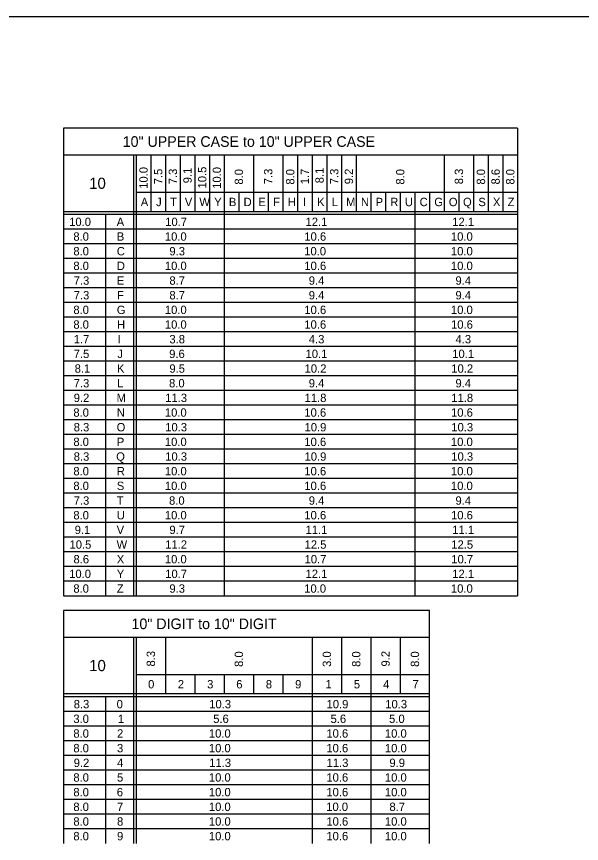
# Model space of a CAD drawing. Extents: x 637580 to 641849, y 297270 to 299646.
# Drawn here: x 640533.1 to 640735.3, y 298740.6 to 299036.6 of the extents above; entities that cross this region are included whole.
import ezdxf

# ---------------------------------------------------------------- set-up
doc = ezdxf.new("R2010")
doc.units = 0
doc.layers.add('1', color=7, linetype='Continuous')
doc.layers.add('2', color=7, linetype='Continuous')

msp = doc.modelspace()

# ---------------------------------------------------------------- linework, layer by layer
at = {"layer": '1'}
msp.add_line((640143.31, 299036.63), (640929.31, 299036.63), dxfattribs=at)
at = {"layer": '2'}
for p, q in [((640712.41, 298996.63), (640549.91, 298996.63)), ((640549.91, 298996.63), (640549.91, 298829.25)), ((640712.41, 298996.63), (640712.41, 298829.25)), ((640549.91, 298987.13), (640712.41, 298987.13)), ((640574.91, 298987.13), (640574.91, 298829.25)), ((640575.91, 298987.13), (640575.91, 298829.25)), ((640581.16, 298987.13), (640581.16, 298966.75)), ((640586.41, 298987.13), (640586.41, 298966.75)), ((640591.66, 298987.13), (640591.66, 298966.75)), ((640596.91, 298987.13), (640596.91, 298966.75)), ((640602.16, 298987.13), (640602.16, 298966.75)), ((640607.41, 298987.13), (640607.41, 298829.25)), ((640617.91, 298987.13), (640617.91, 298966.75)), ((640628.41, 298987.13), (640628.41, 298966.75)), ((640633.66, 298987.13), (640633.66, 298966.75)), ((640638.91, 298987.13), (640638.91, 298966.75)), ((640644.16, 298987.13), (640644.16, 298966.75)), ((640649.41, 298987.13), (640649.41, 298966.75)), ((640654.66, 298987.13), (640654.66, 298966.75)), ((640686.16, 298987.13), (640686.16, 298966.75)), ((640696.66, 298987.13), (640696.66, 298966.75)), ((640701.91, 298987.13), (640701.91, 298966.75)), ((640707.16, 298987.13), (640707.16, 298966.75)), ((640575.91, 298973.75), (640712.41, 298973.75)), ((640612.66, 298973.75), (640612.66, 298966.75)), ((640623.16, 298973.75), (640623.16, 298966.75)), ((640659.91, 298973.75), (640659.91, 298966.75)), ((640665.16, 298973.75), (640665.16, 298966.75)), ((640670.41, 298973.75), (640670.41, 298966.75)), ((640670.41, 298973.75), (640670.41, 298966.75)), ((640675.66, 298973.75), (640675.66, 298829.25)), ((640680.91, 298973.75), (640680.91, 298966.75)), ((640691.41, 298973.75), (640691.41, 298966.75)), ((640712.41, 298966.75), (640549.91, 298966.75)), ((640712.41, 298965.75), (640549.91, 298965.75)), ((640564.91, 298965.75), (640564.91, 298829.25)), ((640712.41, 298960.5), (640549.91, 298960.5)), ((640712.41, 298955.25), (640549.91, 298955.25)), ((640712.41, 298950), (640549.91, 298950)), ((640712.41, 298944.75), (640549.91, 298944.75)), ((640712.41, 298939.5), (640549.91, 298939.5)), ((640712.41, 298934.25), (640549.91, 298934.25)), ((640712.41, 298929), (640549.91, 298929)), ((640712.41, 298923.75), (640549.91, 298923.75)), ((640712.41, 298918.5), (640549.91, 298918.5)), ((640712.41, 298913.25), (640549.91, 298913.25)), ((640712.41, 298908), (640549.91, 298908)), ((640712.41, 298902.75), (640549.91, 298902.75)), ((640712.41, 298897.5), (640549.91, 298897.5)), ((640712.41, 298892.25), (640549.91, 298892.25)), ((640712.41, 298887), (640549.91, 298887)), ((640712.41, 298881.75), (640549.91, 298881.75)), ((640712.41, 298876.5), (640549.91, 298876.5)), ((640712.41, 298871.25), (640549.91, 298871.25)), ((640712.41, 298866), (640549.91, 298866)), ((640712.41, 298860.75), (640549.91, 298860.75)), ((640712.41, 298855.5), (640549.91, 298855.5)), ((640712.41, 298850.25), (640549.91, 298850.25)), ((640712.41, 298845), (640549.91, 298845)), ((640712.41, 298839.75), (640549.91, 298839.75)), ((640712.41, 298834.5), (640549.91, 298834.5)), ((640549.91, 298829.25), (640549.91, 298829.25)), ((640549.91, 298829.25), (640712.41, 298829.25)), ((640680.91, 298824), (640549.91, 298824)), ((640549.91, 298824), (640549.91, 298740.63)), ((640680.91, 298740.63), (640680.91, 298824)), ((640549.91, 298814.5), (640680.91, 298814.5)), ((640574.91, 298814.5), (640574.91, 298740.63)), ((640575.91, 298814.5), (640575.91, 298740.63)), ((640586.41, 298814.5), (640586.41, 298794.13)), ((640638.91, 298814.5), (640638.91, 298740.63)), ((640649.41, 298814.5), (640649.41, 298794.13)), ((640659.91, 298814.5), (640659.91, 298740.63)), ((640670.41, 298814.5), (640670.41, 298794.13)), ((640575.91, 298801.13), (640680.91, 298801.13)), ((640596.91, 298801.13), (640596.91, 298794.13)), ((640607.41, 298801.13), (640607.41, 298794.13)), ((640617.91, 298801.13), (640617.91, 298794.13)), ((640628.41, 298801.13), (640628.41, 298794.13)), ((640680.91, 298794.13), (640549.91, 298794.13)), ((640680.91, 298793.13), (640549.91, 298793.13)), ((640564.91, 298793.13), (640564.91, 298740.63)), ((640680.91, 298787.88), (640549.91, 298787.88)), ((640680.91, 298782.63), (640549.91, 298782.63)), ((640680.91, 298777.38), (640549.91, 298777.38)), ((640680.91, 298772.13), (640549.91, 298772.13)), ((640680.91, 298766.88), (640549.91, 298766.88)), ((640680.91, 298761.63), (640549.91, 298761.63)), ((640680.91, 298756.38), (640549.91, 298756.38)), ((640680.91, 298751.13), (640549.91, 298751.13)), ((640680.91, 298745.88), (640549.91, 298745.88))]:
    msp.add_line(p, q, dxfattribs=at)

# ---------------------------------------------------------------- texts
for s, height, p in [('10" UPPER CASE to 10" UPPER CASE', 3.8, (640571.1, 298989.98)), ('10', 4, (640559.1, 298974.94)), ('A', 3, (640577.56, 298968.75)), ('J', 3, (640583.04, 298968.75)), ('T', 3, (640588.04, 298968.75)), ('V', 3, (640593.31, 298968.75)), ('W', 3, (640598.53, 298968.75)), ('Y', 3, (640603.84, 298968.75)), ('B', 3, (640609.1, 298968.75)), ('D', 3, (640614.35, 298968.75)), ('E', 3, (640619.62, 298968.75)), ('F', 3, (640624.92, 298968.75)), ('H', 3, (640630.19, 298968.75)), ('I', 3, (640635.6, 298968.75)), ('K', 3, (640640.69, 298968.75)), ('L', 3, (640645.94, 298968.75)), ('M', 3, (640651.03, 298968.75)), ('N', 3, (640656.35, 298968.75)), ('P', 3, (640661.6, 298968.75)), ('R', 3, (640666.85, 298968.75)), ('U', 3, (640672.09, 298968.75)), ('C', 3, (640677.35, 298968.75)), ('G', 3, (640682.6, 298968.75)), ('O', 3, (640687.81, 298968.75)), ('Q', 3, (640692.88, 298968.75)), ('S', 3, (640698.37, 298968.75)), ('X', 3, (640703.59, 298968.75)), ('Z', 3, (640708.85, 298968.75)), ('10.0', 3, (640551.93, 298961.63)), ('A', 3, (640568.93, 298961.63)), ('10.7', 3, (640586.31, 298961.63)), ('12.1', 3, (640636.53, 298961.63)), ('12.1', 3, (640689.03, 298961.63)), ('8.0', 3, (640553.43, 298956.38)), ('B', 3, (640568.98, 298956.38)), ('10.0', 3, (640586.18, 298956.38)), ('10.6', 3, (640636.1, 298956.38)), ('10.0', 3, (640688.56, 298956.38)), ('8.0', 3, (640553.43, 298951.13)), ('C', 3, (640568.98, 298951.13)), ('9.3', 3, (640587.81, 298951.13)), ('10.0', 3, (640636.06, 298951.13)), ('10.0', 3, (640688.56, 298951.13)), ('8.0', 3, (640553.43, 298945.88)), ('D', 3, (640568.98, 298945.88)), ('10.0', 3, (640586.18, 298945.88)), ('10.6', 3, (640636.1, 298945.88)), ('10.0', 3, (640688.56, 298945.88)), ('7.3', 3, (640553.56, 298940.63)), ('E', 3, (640568.99, 298940.63)), ('8.7', 3, (640587.81, 298940.63)), ('9.4', 3, (640637.69, 298940.63)), ('9.4', 3, (640690.19, 298940.63)), ('7.3', 3, (640553.56, 298935.38)), ('F', 3, (640569.05, 298935.38)), ('8.7', 3, (640587.81, 298935.38)), ('9.4', 3, (640637.69, 298935.38)), ('9.4', 3, (640690.19, 298935.38)), ('8.0', 3, (640553.43, 298930.13)), ('G', 3, (640568.98, 298930.13)), ('10.0', 3, (640586.18, 298930.13)), ('10.6', 3, (640636.1, 298930.13)), ('10.0', 3, (640688.56, 298930.13)), ('8.0', 3, (640553.43, 298924.88)), ('H', 3, (640569.06, 298924.88)), ('10.0', 3, (640586.18, 298924.88)), ('10.6', 3, (640636.1, 298924.88)), ('10.6', 3, (640688.6, 298924.88)), ('1.7', 3, (640553.56, 298919.63)), ('I', 3, (640569.23, 298919.63)), ('3.8', 3, (640587.81, 298919.63)), ('4.3', 3, (640637.69, 298919.63)), ('4.3', 3, (640690.19, 298919.63)), ('7.5', 3, (640553.56, 298914.38)), ('J', 3, (640569.17, 298914.38)), ('9.6', 3, (640587.73, 298914.38)), ('10.1', 3, (640636.53, 298914.38)), ('10.1', 3, (640689.03, 298914.38)), ('8.1', 3, (640553.9, 298909.13)), ('K', 3, (640569.06, 298909.13)), ('9.5', 3, (640587.81, 298909.13)), ('10.2', 3, (640636.19, 298909.13)), ('10.2', 3, (640688.69, 298909.13)), ('7.3', 3, (640553.56, 298903.88)), ('L', 3, (640569.06, 298903.88)), ('8.0', 3, (640587.68, 298903.88)), ('9.4', 3, (640637.69, 298903.88)), ('9.4', 3, (640690.19, 298903.88)), ('9.2', 3, (640553.56, 298898.63)), ('M', 3, (640568.91, 298898.63)), ('11.3', 3, (640586.31, 298898.63)), ('11.8', 3, (640636.19, 298898.63)), ('11.8', 3, (640688.69, 298898.63)), ('8.0', 3, (640553.43, 298893.38)), ('N', 3, (640568.98, 298893.38)), ('10.0', 3, (640586.18, 298893.38)), ('10.6', 3, (640636.1, 298893.38)), ('10.6', 3, (640688.6, 298893.38)), ('8.3', 3, (640553.56, 298888.13)), ('O', 3, (640568.93, 298888.13)), ('10.3', 3, (640586.31, 298888.13)), ('10.9', 3, (640636.17, 298888.13)), ('10.3', 3, (640688.69, 298888.13)), ('8.0', 3, (640553.43, 298882.88)), ('P', 3, (640568.98, 298882.88)), ('10.0', 3, (640586.18, 298882.88)), ('10.6', 3, (640636.1, 298882.88)), ('10.0', 3, (640688.56, 298882.88)), ('8.3', 3, (640553.56, 298877.63)), ('Q', 3, (640568.75, 298877.63)), ('10.3', 3, (640586.31, 298877.63)), ('10.9', 3, (640636.17, 298877.63)), ('10.3', 3, (640688.69, 298877.63)), ('8.0', 3, (640553.43, 298872.38)), ('R', 3, (640568.98, 298872.38)), ('10.0', 3, (640586.18, 298872.38)), ('10.6', 3, (640636.1, 298872.38)), ('10.0', 3, (640688.56, 298872.38)), ('8.0', 3, (640553.43, 298867.13)), ('S', 3, (640568.99, 298867.13)), ('10.0', 3, (640586.18, 298867.13)), ('10.6', 3, (640636.1, 298867.13)), ('10.0', 3, (640688.56, 298867.13)), ('7.3', 3, (640553.56, 298861.88)), ('T', 3, (640568.92, 298861.88)), ('8.0', 3, (640587.68, 298861.88)), ('9.4', 3, (640637.69, 298861.88)), ('9.4', 3, (640690.19, 298861.88)), ('8.0', 3, (640553.43, 298856.63)), ('U', 3, (640568.97, 298856.63)), ('10.0', 3, (640586.18, 298856.63)), ('10.6', 3, (640636.1, 298856.63)), ('10.6', 3, (640688.6, 298856.63)), ('9.1', 3, (640553.9, 298851.38)), ('V', 3, (640568.93, 298851.38)), ('9.7', 3, (640587.81, 298851.38)), ('11.1', 3, (640636.53, 298851.38)), ('11.1', 3, (640689.03, 298851.38)), ('10.5', 3, (640552.06, 298846.13)), ('W', 3, (640568.91, 298846.13)), ('11.2', 3, (640586.31, 298846.13)), ('12.5', 3, (640636.19, 298846.13)), ('12.5', 3, (640688.69, 298846.13)), ('8.6', 3, (640553.48, 298840.88)), ('X', 3, (640568.97, 298840.88)), ('10.0', 3, (640586.18, 298840.88)), ('10.7', 3, (640636.19, 298840.88)), ('10.7', 3, (640688.69, 298840.88)), ('10.0', 3, (640551.93, 298835.63)), ('10.7', 3, (640586.31, 298835.63)), ('12.1', 3, (640636.53, 298835.63)), ('12.1', 3, (640689.03, 298835.63)), ('Y', 3, (640568.97, 298835.63)), ('8.0', 3, (640553.43, 298830.38)), ('Z', 3, (640568.98, 298830.38)), ('9.3', 3, (640587.81, 298830.38)), ('10.0', 3, (640636.06, 298830.38)), ('10.0', 3, (640688.56, 298830.38)), ('10" DIGIT to 10" DIGIT', 3.8, (640574.26, 298817.35)), ('10', 4, (640559.1, 298802.31)), ('0', 3, (640580.18, 298796.13)), ('2', 3, (640590.81, 298796.13)), ('3', 3, (640601.31, 298796.13)), ('6', 3, (640611.73, 298796.13)), ('8', 3, (640622.31, 298796.13)), ('9', 3, (640632.8, 298796.13)), ('1', 3, (640643.65, 298796.13)), ('5', 3, (640653.81, 298796.13)), ('4', 3, (640664.31, 298796.13)), ('7', 3, (640674.81, 298796.13)), ('8.3', 3, (640553.56, 298789)), ('0', 3, (640568.93, 298789)), ('10.3', 3, (640602.06, 298789)), ('10.9', 3, (640644.05, 298789)), ('10.3', 3, (640665.06, 298789)), ('3.0', 3, (640553.43, 298783.75)), ('1', 3, (640569.4, 298783.75)), ('5.6', 3, (640603.48, 298783.75)), ('5.6', 3, (640645.48, 298783.75)), ('5.0', 3, (640666.43, 298783.75)), ('8.0', 3, (640553.43, 298778.5)), ('2', 3, (640569.06, 298778.5)), ('10.0', 3, (640601.93, 298778.5)), ('10.6', 3, (640643.98, 298778.5)), ('10.0', 3, (640664.93, 298778.5)), ('8.0', 3, (640553.43, 298773.25)), ('3', 3, (640569.06, 298773.25)), ('10.0', 3, (640601.93, 298773.25)), ('10.6', 3, (640643.98, 298773.25)), ('10.0', 3, (640664.93, 298773.25)), ('9.2', 3, (640553.56, 298768)), ('4', 3, (640569.06, 298768)), ('11.3', 3, (640602.06, 298768)), ('11.3', 3, (640644.06, 298768)), ('9.9', 3, (640666.55, 298768)), ('8.0', 3, (640553.43, 298762.75)), ('5', 3, (640569.06, 298762.75)), ('10.0', 3, (640601.93, 298762.75)), ('10.6', 3, (640643.98, 298762.75)), ('10.0', 3, (640664.93, 298762.75)), ('8.0', 3, (640553.43, 298757.5)), ('6', 3, (640568.98, 298757.5)), ('10.0', 3, (640601.93, 298757.5)), ('10.6', 3, (640643.98, 298757.5)), ('10.0', 3, (640664.93, 298757.5)), ('8.0', 3, (640553.43, 298752.25)), ('7', 3, (640569.06, 298752.25)), ('10.0', 3, (640601.93, 298752.25)), ('10.0', 3, (640643.93, 298752.25)), ('8.7', 3, (640666.56, 298752.25)), ('8.0', 3, (640553.43, 298747)), ('8', 3, (640569.06, 298747)), ('10.0', 3, (640601.93, 298747)), ('10.6', 3, (640643.98, 298747)), ('10.0', 3, (640664.93, 298747)), ('8.0', 3, (640553.43, 298741.75)), ('9', 3, (640569.05, 298741.75)), ('10.0', 3, (640601.93, 298741.75)), ('10.6', 3, (640643.98, 298741.75)), ('10.0', 3, (640664.93, 298741.75))]:
    msp.add_text(s, height=height, dxfattribs=at).set_placement(p)
for s, p in [('10.0', (640580.04, 298974.96)), ('7.5', (640585.29, 298976.59)), ('7.3', (640590.54, 298976.59)), ('9.1', (640595.79, 298976.93)), ('10.5', (640601.04, 298975.09)), ('10.0', (640606.29, 298974.96)), ('8.0', (640614.16, 298976.46)), ('7.3', (640624.66, 298976.59)), ('8.0', (640632.54, 298976.46)), ('1.7', (640637.79, 298976.59)), ('8.1', (640643.04, 298976.93)), ('7.3', (640648.29, 298976.59)), ('9.2', (640653.54, 298976.59)), ('8.0', (640671.91, 298976.46)), ('8.3', (640692.91, 298976.59)), ('8.0', (640700.79, 298976.46)), ('8.6', (640706.04, 298976.51)), ('8.0', (640711.29, 298976.46)), ('8.3', (640582.66, 298803.96)), ('8.0', (640614.16, 298803.83)), ('3.0', (640645.66, 298803.83)), ('8.0', (640656.16, 298803.83)), ('9.2', (640666.66, 298803.96)), ('8.0', (640677.16, 298803.83))]:
    msp.add_text(s, height=3, rotation=90, dxfattribs=at).set_placement(p)

doc.saveas('drawing.dxf')
